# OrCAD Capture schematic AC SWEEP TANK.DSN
size A
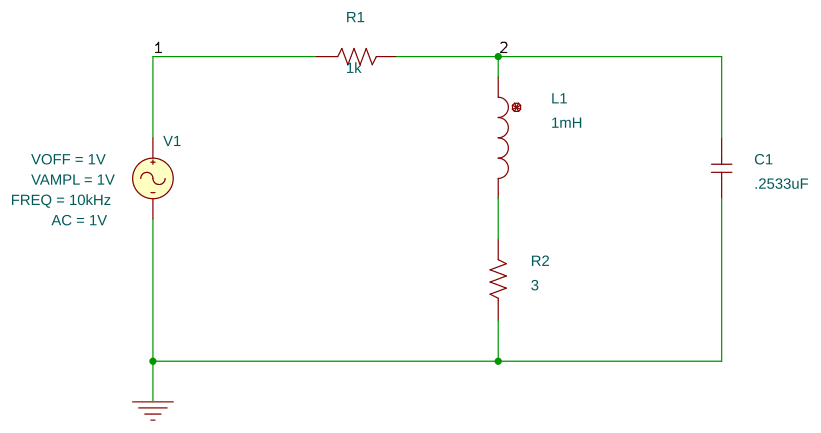
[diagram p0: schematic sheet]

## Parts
C1  .2533uF  [RAD/CK05]
L1  1mH  [DISC/.350x.175/LS.200x.100/.034]
R1  1k  [AX/RC05]
R2  3  [AX/RC05]
V1  VSIN

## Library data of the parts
C1 = C
L1 = L
R1 R2 = R
V1 = VSIN: AC: 1V; FREQ: 10kHz; VAMPL: 1V; VOFF: 1V

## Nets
0: C1.1 R2.1 V1.2(-)
1: R1.1 V1.1(+)
2: C1.2 L1.1 R1.2
N14446: L1.2 R2.2
